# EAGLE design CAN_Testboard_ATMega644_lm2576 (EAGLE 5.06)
VOLTAGE: 16V

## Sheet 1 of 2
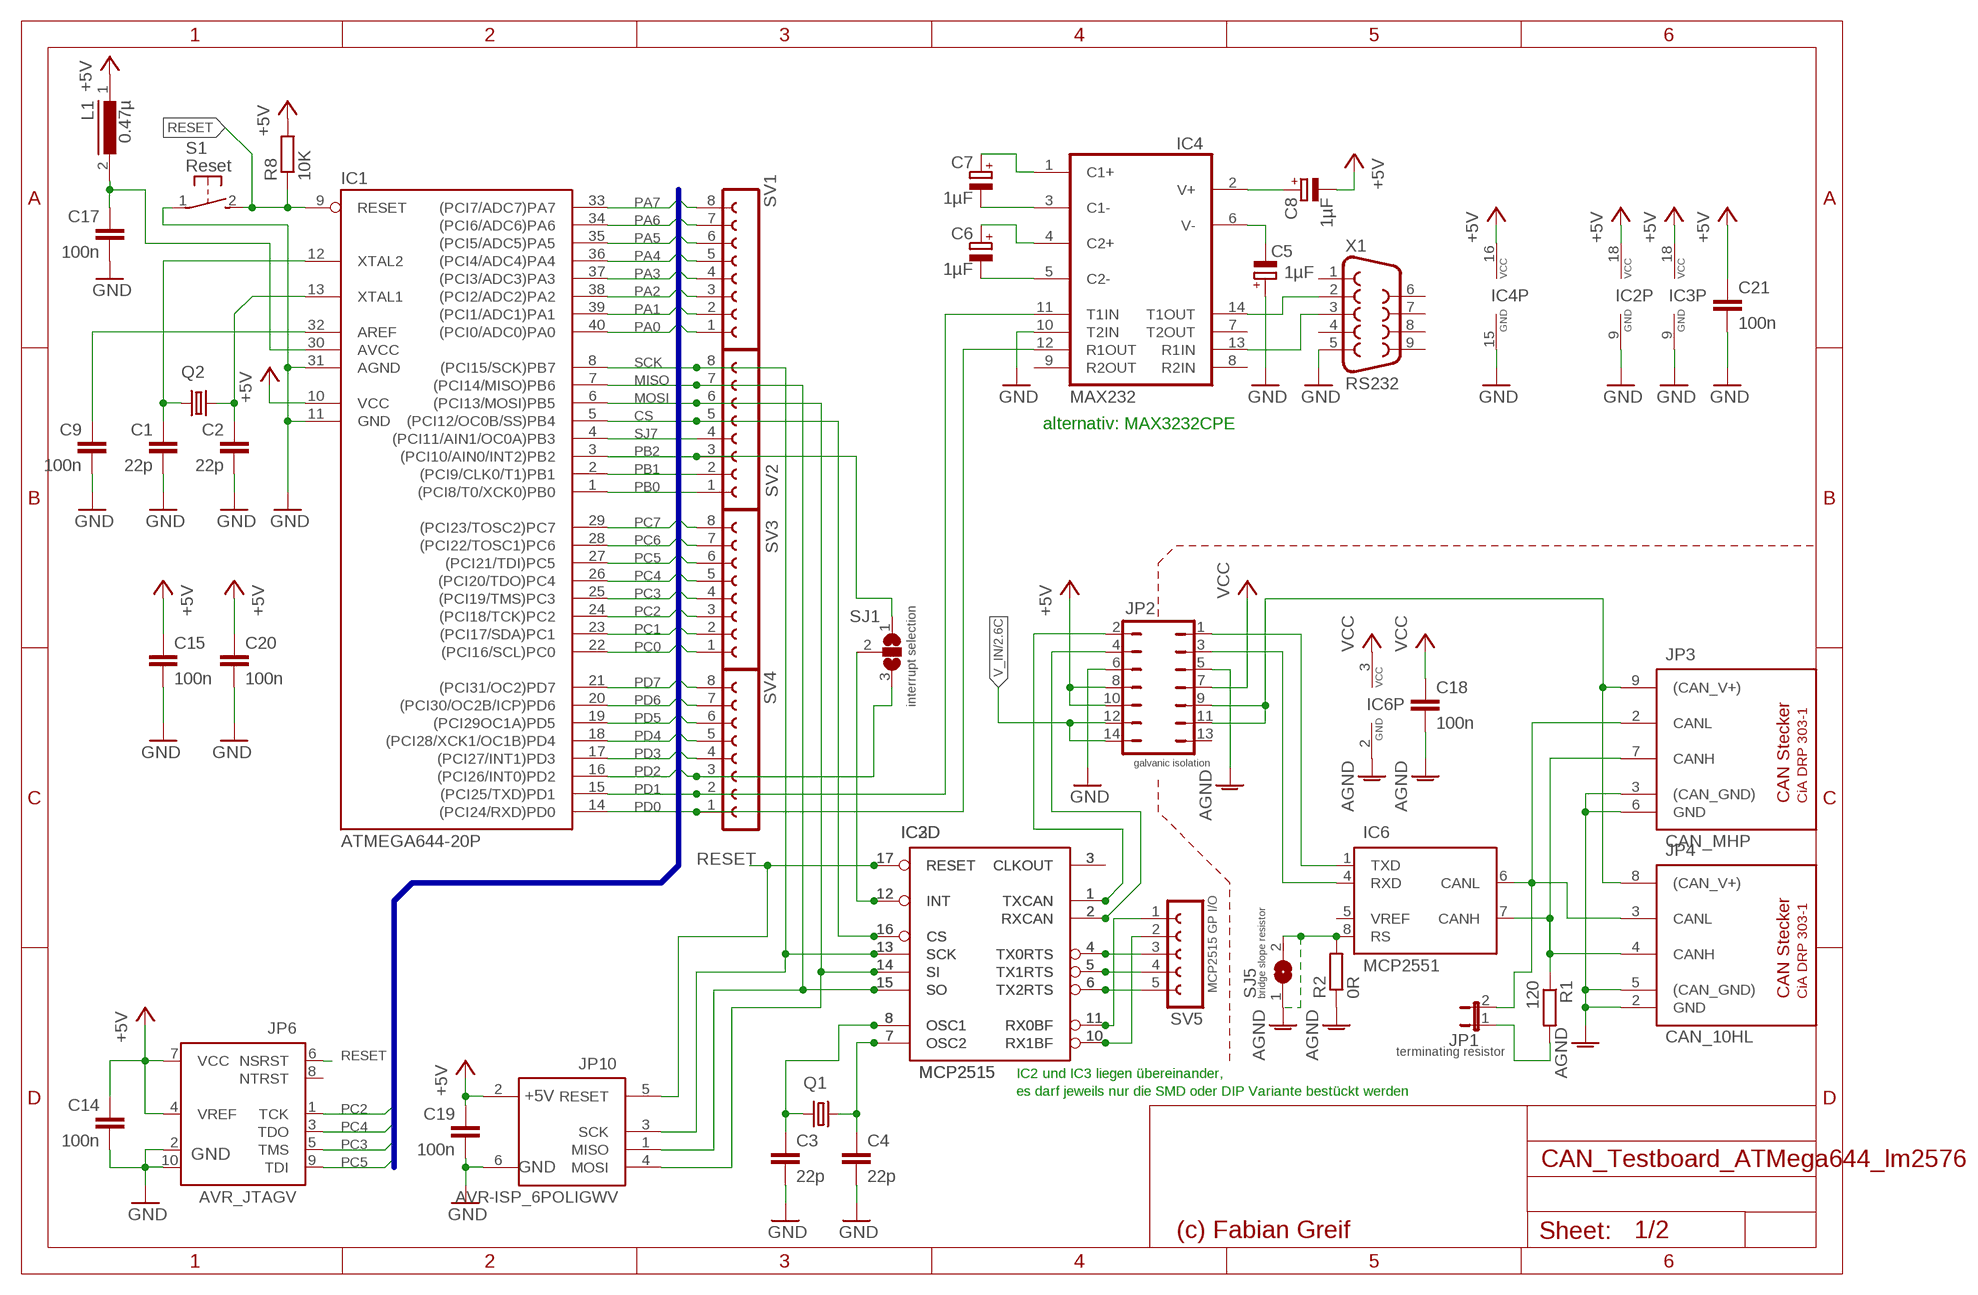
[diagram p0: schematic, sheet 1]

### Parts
C1  22p  C-EU025-024X044  [C025-024X044]
C2  22p  C-EU025-024X044  [C025-024X044]
C3  22p  C-EU025-024X044  [C025-024X044]
C4  22p  C-EU025-024X044  [C025-024X044]
C5  1µF  CPOL-EUE2.5-5  [E2,5-5]
C6  1µF  CPOL-EUE2.5-5  [E2,5-5]
C7  1µF  CPOL-EUE2.5-5  [E2,5-5]
C8  1µF  CPOL-EUE2.5-5  [E2,5-5]
C9  100n  C-EU025-024X044  [C025-024X044]
C14  100n  C-EU025-024X044  [C025-024X044]
C15  100n  C-EU025-024X044  [C025-024X044]
C17  100n  C-EU025-024X044  [C025-024X044]
C18  100n  C-EU025-024X044  [C025-024X044]
C19  100n  C-EU025-024X044  [C025-024X044]
C20  100n  C-EU025-024X044  [C025-024X044]
C21  100n  C-EU025-024X044  [C025-024X044]
IC1  ATMEGA644-20P  [DIL40]
IC2  MCP2515  MCP2515P  [DIL18]
IC3  MCP2515  MCP2515SO  [SO-18W]
IC4  MAX232  [DIL16]
IC6  MCP2551  PCA82C250  [DIL08]
JP1  terminating resistor  JP1E  [JP1]
JP2  galvanic isolation  JP7Q  [JP7Q]
JP3  CAN_MHP  [M09HP]
JP4  CAN_10HL  [ML10L]
JP6  AVR_JTAGV  [ML10L]
JP10  AVR-ISP_6POLIGWV  [ML6L]
L1  0.47µ  BC12  [BC12]
Q1  16.000  CRYTALHC49U-V  [HC49U-V]
Q2  14.7456  CRYTALHC49U-V  [HC49U-V]
R1  120  R-EU_0207/7  [0207/7]
R2  0R  R-EU_0207/7  [0207/7]
R8  10K  R-EU_0207/7  [0207/7]
S1  Reset  31-XX  [B3F-31XX]
SJ1  interrupt selection  SJ2W  [SJ_2]
SJ5  bridge slope resistor  SJ  [SJ]
SV1  Port A  FE08-1  [FE08]
SV2  Port B  FE08-1  [FE08]
SV3  Port C  FE08-1  [FE08]
SV4  Port D  FE08-1  [FE08]
SV5  MCP2515 GP I/O  FE05-1  [FE05-1]
X1  RS232  F09HP  [F09HP]

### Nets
+5V: C8.- C14.1 C15.1 C19.1 C20.1 C21.1 IC1.10(VCC) IC2.18(P:VCC) IC3.18(P:VCC) IC4.16(VCC) JP2.8 JP2.10 JP6.4(VREF) JP6.7(VCC) JP10.2(+5V) L1.1 R8.2 ; also sheet 2
AGND: C18.2 IC6.2(GND) JP2.5 JP3.3((CAN_GND)) JP3.6(GND) JP4.2(GND) JP4.5((CAN_GND)) R2.1 SJ5.1
AVCC: C17.1 IC1.30(AVCC) L1.2
CLKOUT: C2.1 IC1.13(XTAL1) Q2.2
CLKOUT1: IC2.3(D:CLKOUT) IC3.3(D:CLKOUT)
CS: IC1.5((PCI12/OC0B/SS)PB4) IC2.16(D:CS) IC3.16(D:CS) SV2.5 ; also sheet 2
GND: C1.2 C2.2 C3.2 C4.2 C5.+ C9.2 C14.2 C15.2 C17.2 C19.2 C20.2 C21.2 IC1.11(GND) IC1.31(AGND) IC2.9(P:GND) IC3.9(P:GND) IC4.10(T2IN) IC4.15(GND) JP2.6 JP6.2(GND) JP6.10(GND) JP10.6(GND) S1.1(P) X1.5 ; also sheet 2
MISO: IC1.7((PCI14/MISO)PB6) IC2.15(D:SO) IC3.15(D:SO) JP10.1(MISO) SV2.7 ; also sheet 2
MOSI: IC1.6((PCI13/MOSI)PB5) IC2.14(D:SI) IC3.14(D:SI) JP10.4(MOSI) SV2.6 ; also sheet 2
N$1: C6.- IC4.5(C2-)
N$2: C6.+ IC4.4(C2+)
N$3: C7.- IC4.3(C1-)
N$4: C8.+ IC4.2(V+)
N$5: C5.- IC4.6(V-)
N$8: C7.+ IC4.1(C1+)
N$9: C4.1 IC2.7(D:OSC2) IC3.7(D:OSC2) Q1.2
N$10: IC6.4(RXD) JP2.3
N$11: IC2.2(D:RXCAN) IC3.2(D:RXCAN) JP2.4
N$12: C3.1 IC2.8(D:OSC1) IC3.8(D:OSC1) Q1.1
N$13: C9.1 IC1.32(AREF)
N$17: IC6.8(RS) R2.2 SJ5.2
N$18: C1.1 IC1.12(XTAL2) Q2.1
N$20: IC2.12(D:INT) IC3.12(D:INT) SJ1.2
N$22: IC6.6(CANL) JP1.2 JP3.2(CANL) JP4.3(CANL)
N$23: IC6.7(CANH) JP3.7(CANH) JP4.4(CANH) R1.1
N$24: IC6.1(TXD) JP2.1
N$25: JP1.1 R1.2
N$26: IC2.4(D:TX0RTS) IC3.4(D:TX0RTS) SV5.3
N$27: IC2.5(D:TX1RTS) IC3.5(D:TX1RTS) SV5.4
N$28: IC2.6(D:TX2RTS) IC3.6(D:TX2RTS) SV5.5
N$29: IC2.11(D:RX0BF) IC3.11(D:RX0BF) SV5.1
N$30: IC2.10(D:RX1BF) IC3.10(D:RX1BF) SV5.2
N$31: IC2.1(D:TXCAN) IC3.1(D:TXCAN) JP2.2
PA0: IC1.40((PCI0/ADC0)PA0) SV1.1 ; also sheet 2
PA1: IC1.39((PCI1/ADC1)PA1) SV1.2 ; also sheet 2
PA2: IC1.38((PCI2/ADC2)PA2) SV1.3 ; also sheet 2
PA3: IC1.37((PCI3/ADC3)PA3) SV1.4 ; also sheet 2
PA4: IC1.36((PCI4/ADC4)PA4) SV1.5 ; also sheet 2
PA5: IC1.35((PCI5/ADC5)PA5) SV1.6 ; also sheet 2
PA6: IC1.34((PCI6/ADC6)PA6) SV1.7 ; also sheet 2
PA7: IC1.33((PCI7/ADC7)PA7) SV1.8 ; also sheet 2
PB0: IC1.1((PCI8/T0/XCK0)PB0) SV2.1 ; also sheet 2
PB1: IC1.2((PCI9/CLK0/T1)PB1) SV2.2 ; also sheet 2
PB2: IC1.3((PCI10/AIN0/INT2)PB2) SJ1.1 SV2.3 ; also sheet 2
PC0: IC1.22((PCI16/SCL)PC0) SV3.1 ; also sheet 2
PC1: IC1.23((PCI17/SDA)PC1) SV3.2 ; also sheet 2
PC2: IC1.24((PCI18/TCK)PC2) JP6.1(TCK) SV3.3 ; also sheet 2
PC3: IC1.25((PCI19/TMS)PC3) JP6.5(TMS) SV3.4 ; also sheet 2
PC4: IC1.26((PCI20/TDO)PC4) JP6.3(TDO) SV3.5 ; also sheet 2
PC5: IC1.27((PCI21/TDI)PC5) JP6.9(TDI) SV3.6 ; also sheet 2
PC6: IC1.28((PCI22/TOSC1)PC6) SV3.7 ; also sheet 2
PC7: IC1.29((PCI23/TOSC2)PC7) SV3.8 ; also sheet 2
PD0: IC1.14((PCI24/RXD)PD0) IC4.12(R1OUT) SV4.1 ; also sheet 2
PD1: IC1.15((PCI25/TXD)PD1) IC4.11(T1IN) SV4.2 ; also sheet 2
PD2: IC1.16((PCI26/INT0)PD2) SJ1.3 SV4.3 ; also sheet 2
PD3: IC1.17((PCI27/INT1)PD3) SV4.4 ; also sheet 2
PD4: IC1.18((PCI28/XCK1/OC1B)PD4) SV4.5 ; also sheet 2
PD5: IC1.19((PCI29OC1A)PD5) SV4.6 ; also sheet 2
PD6: IC1.20((PCI30/OC2B/ICP)PD6) SV4.7 ; also sheet 2
PD7: IC1.21((PCI31/OC2)PD7) SV4.8 ; also sheet 2
R_IN: IC4.13(R1IN) X1.3
RESET: IC1.9(RESET) IC2.17(D:RESET) IC3.17(D:RESET) JP6.6(NSRST) JP10.5(RESET) R8.1 S1.2(S)
SCK: IC1.8((PCI15/SCK)PB7) IC2.13(D:SCK) IC3.13(D:SCK) JP10.3(SCK) SV2.8 ; also sheet 2
SJ7: IC1.4((PCI11/AIN1/OC0A)PB3) SV2.4 ; also sheet 2
T_OUT: IC4.14(T1OUT) X1.2
V_CAN: JP2.9 JP2.11 JP3.9((CAN_V+)) JP4.8((CAN_V+))
V_IN: JP2.12 JP2.14 ; also sheet 2
VCC: C18.1 IC6.3(VCC) JP2.7
Unconnected: IC4.7(T2OUT) IC4.8(R2IN) IC4.9(R2OUT) IC6.5(VREF) JP2.13 JP6.8(NTRST) X1.1 X1.4 X1.6 X1.7 X1.8 X1.9

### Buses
PA[0..7],PC[0..7],PD[0..7]

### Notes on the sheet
- alternativ: MAX3232CPE
- IC2 und IC3 liegen übereinander,
- es darf jeweils nur die SMD oder DIP Variante bestückt werden
- (c) Fabian Greif

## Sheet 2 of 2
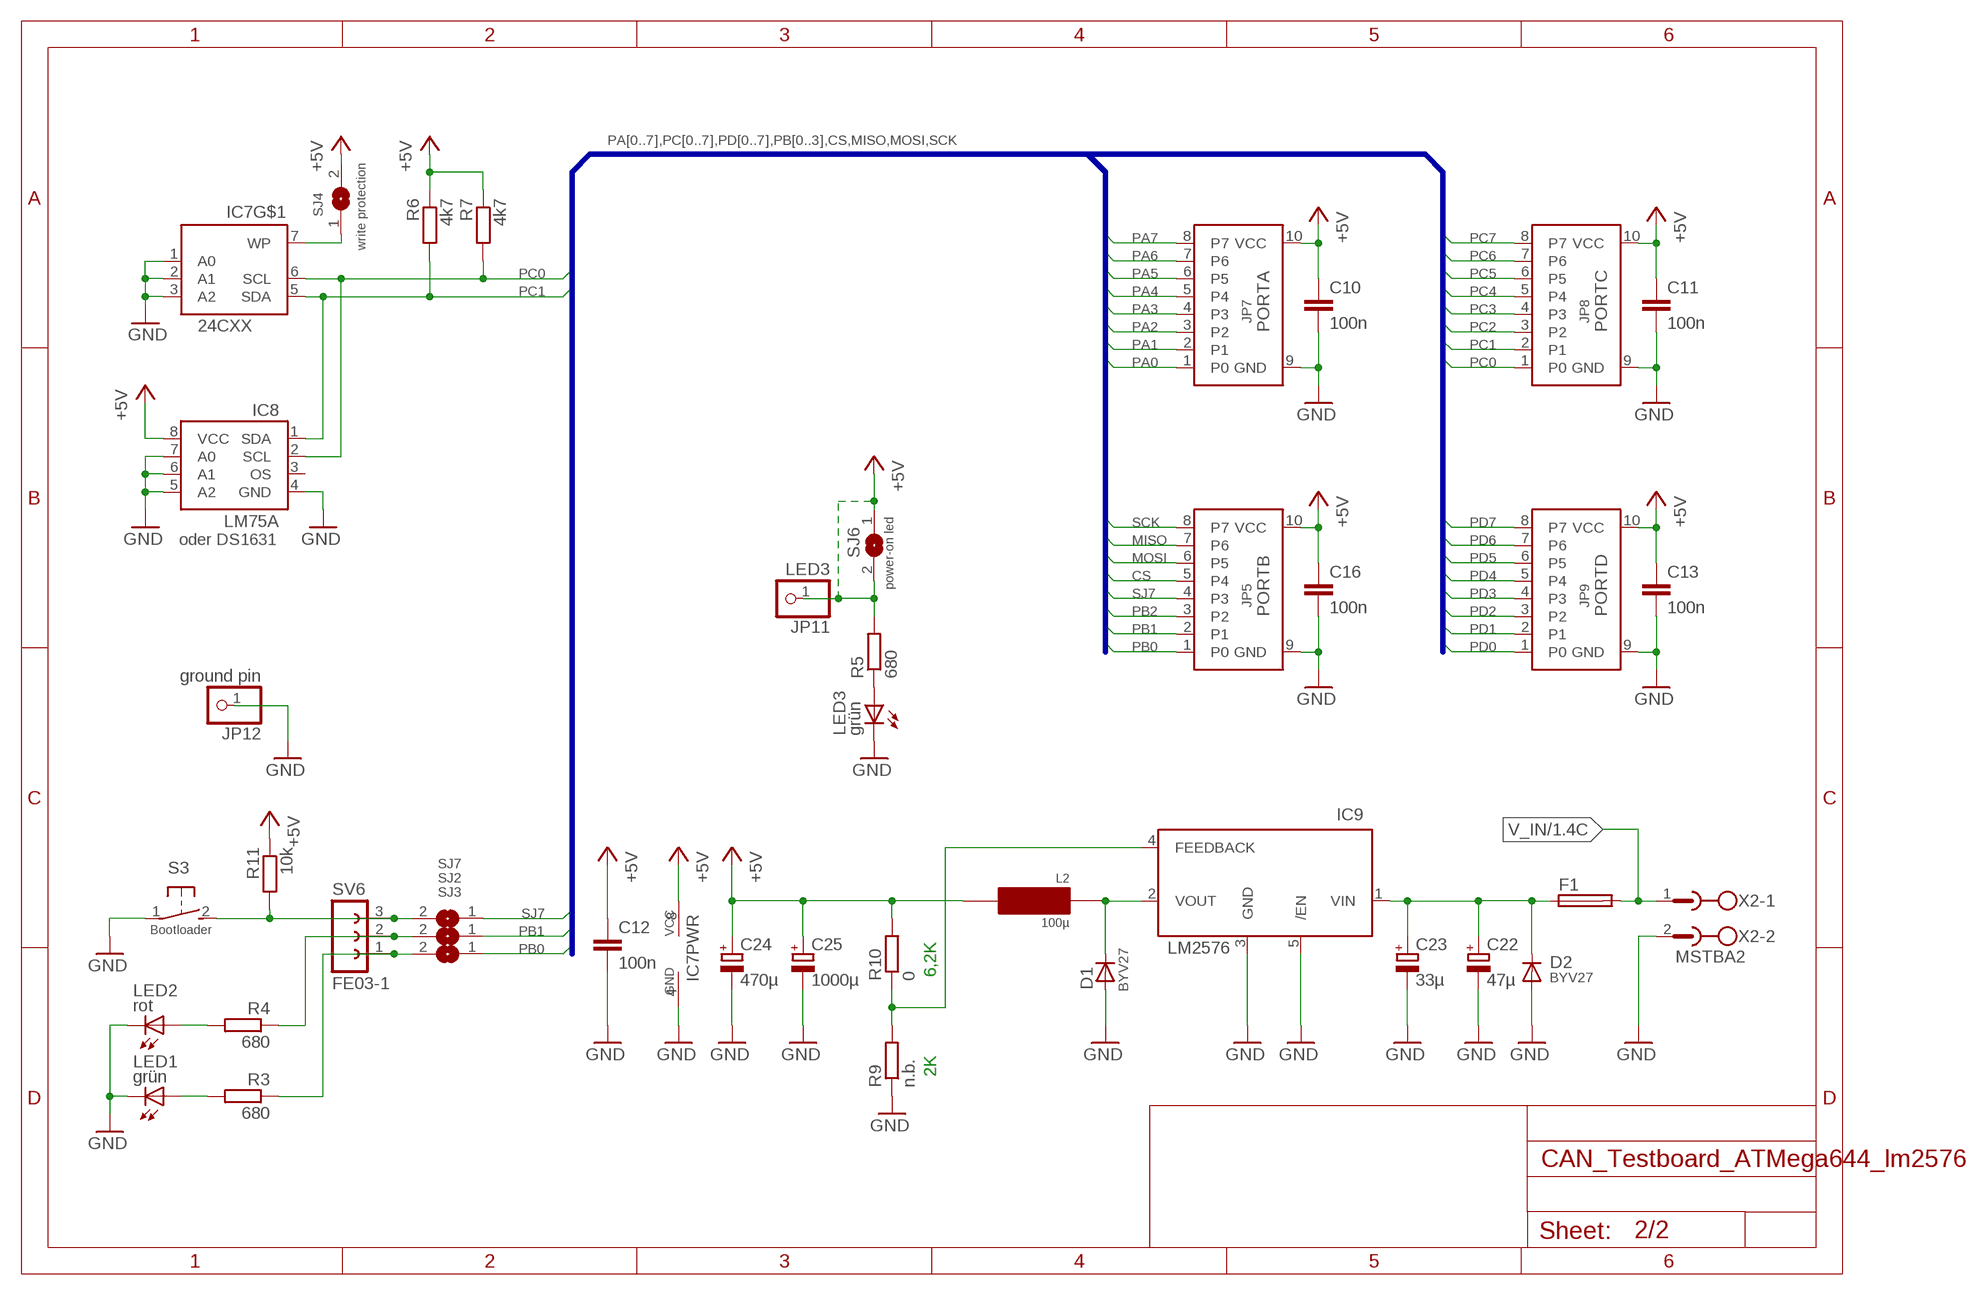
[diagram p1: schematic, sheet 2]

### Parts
C10  100n  C-EU025-024X044  [C025-024X044]
C11  100n  C-EU025-024X044  [C025-024X044]
C12  100n  C-EU025-024X044  [C025-024X044]
C13  100n  C-EU025-024X044  [C025-024X044]
C16  100n  C-EU025-024X044  [C025-024X044]
C22  47µ  CPOL-EUE  [PANASONIC_E]
C23  33µ  CPOL-EUD  [PANASONIC_D]
C24  470µ  CPOL-EUF  [PANASONIC_F]
C25  1000µ  CPOL-EUG  [PANASONIC_G]
D1  BYV27  [SOD57-10]
D2  BYV27  [SOD57-10]
F1  FUSE-SMD  [SMD-HASF]
IC7  24CXX  ST24CXX_SMD  [SO-08]
IC8  LM75A  [SO8]
IC9  LM2576  [TO220-52]
JP5  PORTB  PORT  [ML10]
JP7  PORTA  PORT  [ML10]
JP8  PORTC  PORT  [ML10]
JP9  PORTD  PORT  [ML10]
JP11  LED3  PINHD-1X1  [1X01]
JP12  ground pin  PINHD-1X1  [1X01]
L2  100µ  INDUCTOR-PIS47XX  [L-PIS47XX]
LED1  grün  LED3MM  [LED3MM]
LED2  rot  LED3MM  [LED3MM]
LED3  grün  LED3MM  [LED3MM]
R3  680  R-EU_0207/7  [0207/7]
R4  680  R-EU_0207/7  [0207/7]
R5  680  R-EU_0207/7  [0207/7]
R6  4k7  R-EU_0207/7  [0207/7]
R7  4k7  R-EU_0207/7  [0207/7]
R9  n.b.  R-EU_0207/7  [0207/7]
R10  0  R-EU_0207/7  [0207/7]
R11  10k  R-EU_0207/7  [0207/7]
S3  Bootloader  31-XX  [B3F-31XX]
SJ2  enable LED2  SJ  [SJ]
SJ3  enable LED1  SJ  [SJ]
SJ4  write protection  SJ  [SJ]
SJ6  power-on led  SJ  [SJ]
SJ7  enable S3  SJ  [SJ]
SV6  FE03-1  [FE03-1]
X2  MSTBA2  [MSTBA2]

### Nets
+5V: C10.1 C11.1 C12.1 C13.1 C16.1 C24.+ C25.+ IC7.8(PWR:VCC) IC8.8(VCC) JP5.10(VCC) JP7.10(VCC) JP8.10(VCC) JP9.10(VCC) JP11.1 L2.2 R5.2 R6.1 R7.1 R10.2 R11.1 SJ4.2 SJ6.1 SJ6.2 ; also sheet 1
CS: JP5.5(P4) ; also sheet 1
GND: C10.2 C11.2 C12.2 C13.2 C16.2 C22.- C23.- C24.- C25.- D1.A D2.A IC7.1(A0) IC7.2(A1) IC7.3(A2) IC7.4(PWR:GND) IC8.4(GND) IC8.5(A2) IC8.6(A1) IC8.7(A0) IC9.3(GND) IC9.5(/EN) JP5.9(GND) JP7.9(GND) JP8.9(GND) JP9.9(GND) JP12.1 LED1.K(C) LED2.K(C) LED3.K(C) R9.1 S3.1(P) X2.2 ; also sheet 1
LED4: R4.1 SJ2.2 SV6.2
LED5: R3.1 SJ3.2 SV6.1
MISO: JP5.7(P6) ; also sheet 1
MOSI: JP5.6(P5) ; also sheet 1
N$15: LED3.A R5.1
N$16: C22.+ C23.+ D2.C F1.1 IC9.1(VIN)
N$19: IC9.4(FEEDBACK) R9.2 R10.1
N$48: IC7.7(WP) SJ4.1
N$105: D1.C IC9.2(VOUT) L2.1
N$108: R11.2 S3.2(S) SJ7.2 SV6.3
N$168: LED2.A R4.2
N$169: LED1.A R3.2
PA0: JP7.1(P0) ; also sheet 1
PA1: JP7.2(P1) ; also sheet 1
PA2: JP7.3(P2) ; also sheet 1
PA3: JP7.4(P3) ; also sheet 1
PA4: JP7.5(P4) ; also sheet 1
PA5: JP7.6(P5) ; also sheet 1
PA6: JP7.7(P6) ; also sheet 1
PA7: JP7.8(P7) ; also sheet 1
PB0: JP5.1(P0) SJ3.1 ; also sheet 1
PB1: JP5.2(P1) SJ2.1 ; also sheet 1
PB2: JP5.3(P2) ; also sheet 1
PC0: IC7.6(SCL) IC8.2(SCL) JP8.1(P0) R7.2 ; also sheet 1
PC1: IC7.5(SDA) IC8.1(SDA) JP8.2(P1) R6.2 ; also sheet 1
PC2: JP8.3(P2) ; also sheet 1
PC3: JP8.4(P3) ; also sheet 1
PC4: JP8.5(P4) ; also sheet 1
PC5: JP8.6(P5) ; also sheet 1
PC6: JP8.7(P6) ; also sheet 1
PC7: JP8.8(P7) ; also sheet 1
PD0: JP9.1(P0) ; also sheet 1
PD1: JP9.2(P1) ; also sheet 1
PD2: JP9.3(P2) ; also sheet 1
PD3: JP9.4(P3) ; also sheet 1
PD4: JP9.5(P4) ; also sheet 1
PD5: JP9.6(P5) ; also sheet 1
PD6: JP9.7(P6) ; also sheet 1
PD7: JP9.8(P7) ; also sheet 1
SCK: JP5.8(P7) ; also sheet 1
SJ7: JP5.4(P3) SJ7.1 ; also sheet 1
V_IN: F1.2 X2.1 ; also sheet 1
Unconnected: IC8.3(OS)

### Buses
PA[0..7],PC[0..7],PD[0..7],PB[0..3],CS,MISO,MOSI,SCK

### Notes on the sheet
- oder DS1631
- 6,2K
- 2K

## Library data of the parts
C1-C4 C9-C21 = rcl:C-EU: CAPACITOR, European symbol
C5-C8 C22-C25 = rcl:CPOL-EU: POLARIZED CAPACITOR, European symbol
D1 D2 = diode:BYV27: DIODE
F1 = rca_sontiges:FUSE: Fuse
IC1 = avr:ATMEGA644*P: MICROCONTROLLER 64 kBytes FLASH 4 kBytes SRAM 2 kBytes EEPROM DUAL USART 8-channel 10 bit ADC
IC2 = andereBauteile:MCP2515: MC2515 Stand-Alone CAN Controller With SPI Interface
IC3 = rca_ic:MCP2515: MC2515 Stand-Alone CAN Controller With SPI Interface
IC4 = maxim:MAX232: RS232 TRANSEIVER
IC6 = andereBauteile:PCA82C250: PCA82C250 CAN Bustreiber
IC7 = rca_sontiges:ST24CXX: I²C EEPROM Bei den Atmeltypen ist der A2-Pin nicht angeschlossen! Bisher überprüfte Größen: ST24C32 (4 kByte) ST24C64 (8 kByte) ST24C128 (16 kByte) ST24C256 (32 kByte)
IC8 = nxp:LM75A
IC9 = rca_spgversorgung:LM257*: LM2575/6 1/3A Step-Down Voltage Regulator
JP1 = jumper:JP1E: JUMPER
JP2 = jumper:JP7Q: JUMPER
JP3 JP4 = rca_stecker:CAN_: CAN Stecker nach CiA DRP 303-1
JP5 JP7-JP9 = stecker-definitionen:PORT: Datenportstecker Kompatibel zu den Steckern des STK500
JP6 = stecker-definitionen:AVR_JTAG: AVR JTAG Adapter Zum Programmieren/Simulieren von AVRs in der Schaltung
JP10 = rca_stecker:AVR-ISP_6POLIG: ISP (In System Programming) Stecker für AVRs Über diesen Anschluß kann ein AVR mit einem Standard ISP-Kabel direkt an einen Parallelport des PC´s angeschlossen und programmiert werden.
JP11 JP12 = pinhead:PINHD-1X1: PIN HEADER
L1 = inductors:BC12: INDUCTOR
L2 = rca_sontiges:INDUCTOR: SMD-Power-Induktivitäten
LED1-LED3 = led:LED: LED
Q1 Q2 = crystal:CRYTAL: CRYSTAL
R1-R11 = rcl:R-EU_: RESISTOR, European symbol
S1 S3 = switch-omron:31-XX: OMRON SWITCH
SJ1 = jumper:SJ2W: SMD solder JUMPER
SJ2-SJ7 = jumper:SJ: SMD solder JUMPER
SV1-SV4 = con-lsta:FE08-1: FEMALE HEADER
SV5 = con-lsta:FE05-1: FEMALE HEADER
SV6 = con-lsta:FE03-1
X1 = con-subd:F09: SUB-D
X2 = con-phoenix-508:MSTBA2: PHOENIX

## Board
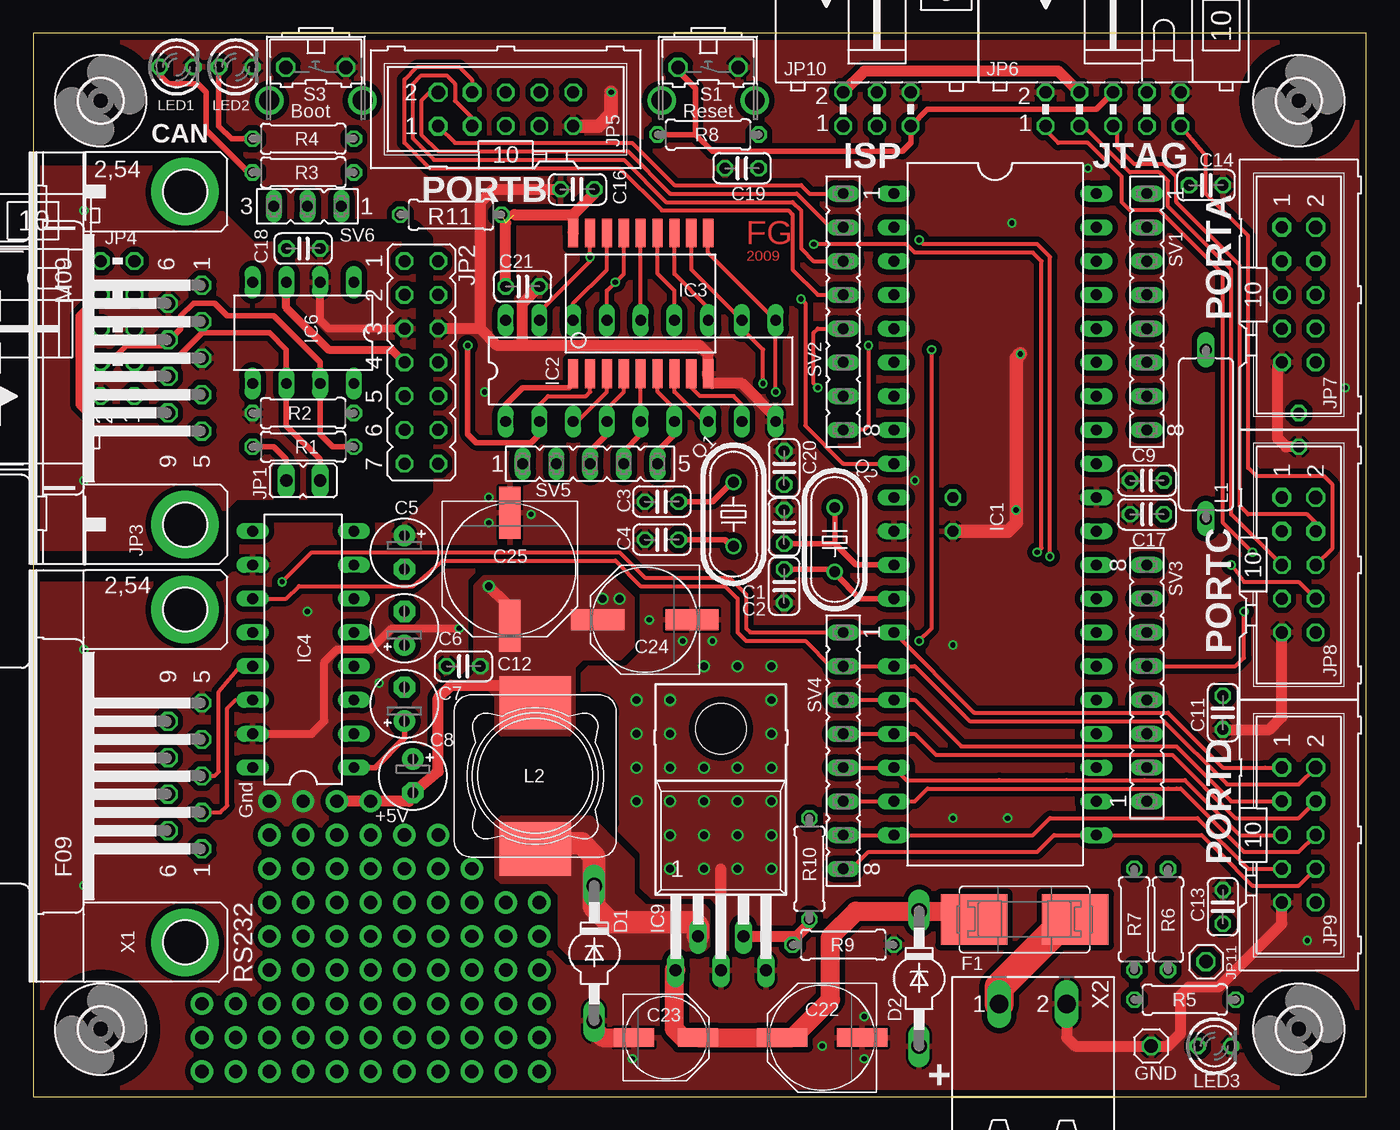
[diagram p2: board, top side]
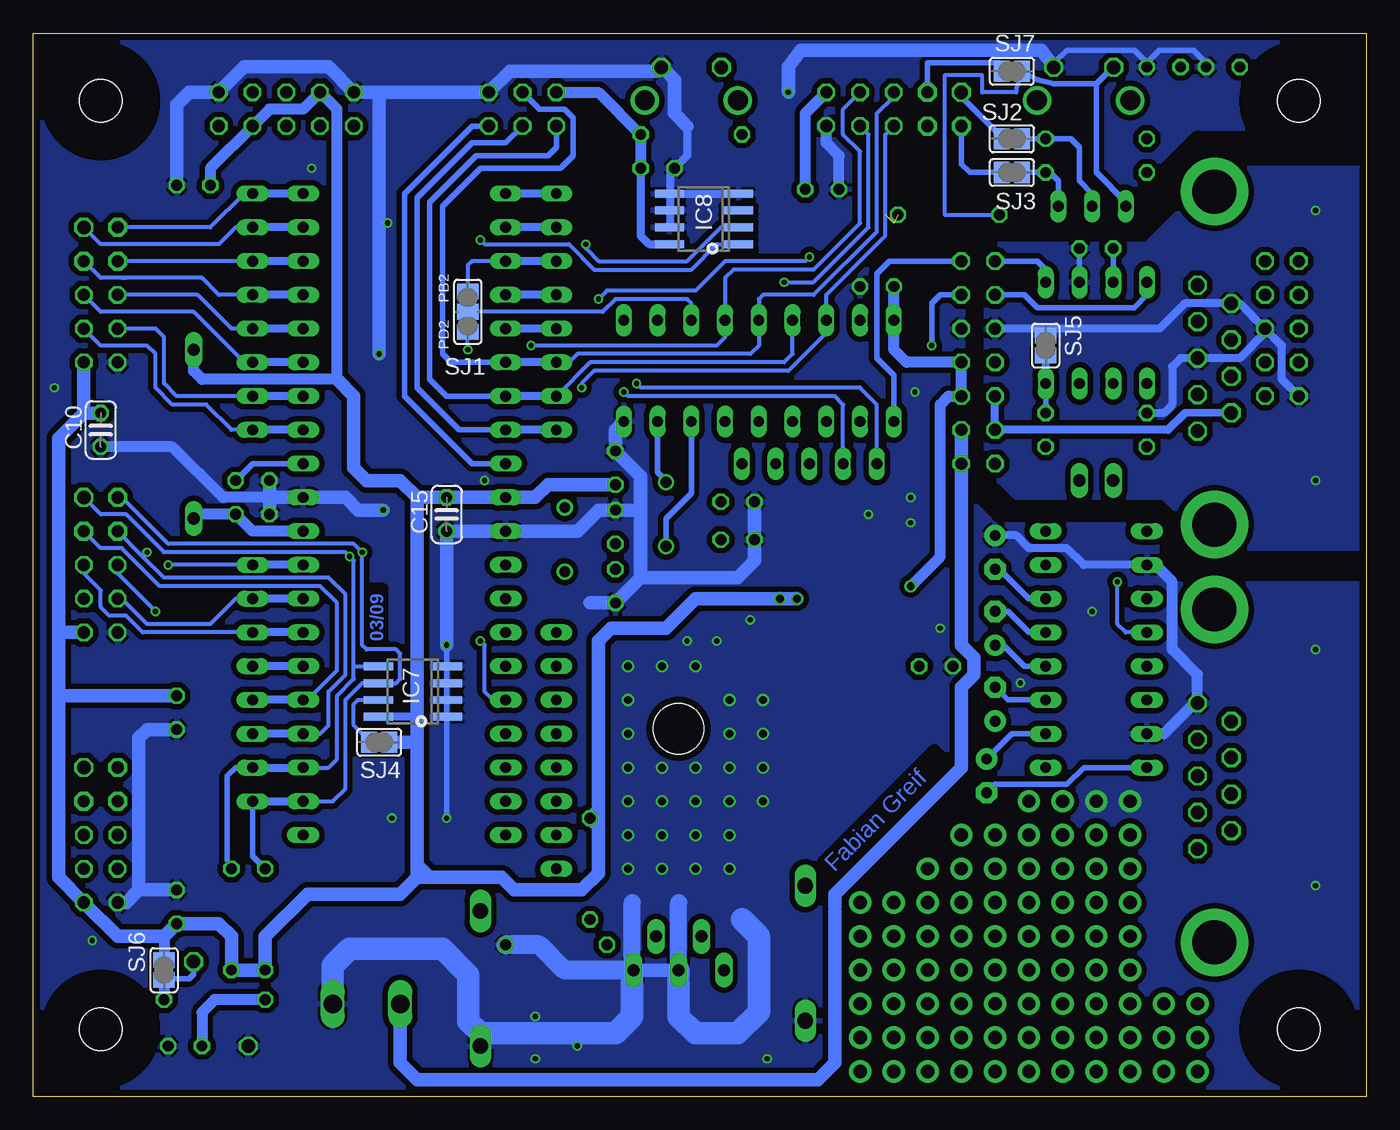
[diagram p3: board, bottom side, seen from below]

Size 100.33 x 80.01 mm. Coordinates in mm from the lower left corner, seen from the top.
Outline: 0,0 100.33,0 100.33,80.01 0,80.01 0,0
Copper layers (1*16): Top 0.035mm / dielectric 1.5mm / Bottom 0.035mm
Design rules "PCB-POOL": minimum track width 6mil, minimum drill 12mil, track to track 6mil, track to pad 6mil, pad to pad 6mil, via to via 6mil, smd to smd 6mil, copper to edge 20mil, drill to drill 8mil, minimum pad ring 8mil, minimum via ring 6mil, stop-mask expansion 3mil, vias tented up to drill 20mil, thermal gap 8mil
tRestrict: 22 lines
bRestrict: 14 lines

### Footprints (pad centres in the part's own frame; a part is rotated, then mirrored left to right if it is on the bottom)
C025-024X044 = drill 0.813 octagon: 1 -1.27,0; 2 1.27,0
E2,5-5 = drill 0.813 pad 1.6 round: + -1.27,0 | drill 0.813 pad 1.6 octagon: - 1.27,0
PANASONIC_E = smd 3.8 x 1.4: + 3,0; - -3,0
PANASONIC_D = smd 3 x 1.4: + 2.4,0; - -2.4,0
PANASONIC_F = smd 4 x 1.6: + 3.55,0; - -3.55,0
PANASONIC_G = smd 3.9 x 1.6: + 4.25,0; - -4.25,0
SOD57-10 = drill 1.194 long: A 5.08,0; C -5.08,0
SMD-HASF = smd 5 x 3.81: 1 -3.81,0; 2 3.81,0
DIL40 = drill 0.813 long: 1 -24.13,-7.62; 2 -21.59,-7.62; 3 -19.05,-7.62; 4 -16.51,-7.62; 5 -13.97,-7.62; 6 -11.43,-7.62; 7 -8.89,-7.62; 8 -6.35,-7.62; 9 -3.81,-7.62; 10 -1.27,-7.62; 11 1.27,-7.62; 12 3.81,-7.62; 13 6.35,-7.62; 14 8.89,-7.62; 15 11.43,-7.62; 16 13.97,-7.62; 17 16.51,-7.62; 18 19.05,-7.62; 19 21.59,-7.62; 20 24.13,-7.62; 21 24.13,7.62; 22 21.59,7.62; 23 19.05,7.62; 24 16.51,7.62; 25 13.97,7.62; 26 11.43,7.62; 27 8.89,7.62; 28 6.35,7.62; 29 3.81,7.62; 30 1.27,7.62; 31 -1.27,7.62; 32 -3.81,7.62; 33 -6.35,7.62; 34 -8.89,7.62; 35 -11.43,7.62; 36 -13.97,7.62; 37 -16.51,7.62; 38 -19.05,7.62; 39 -21.59,7.62; 40 -24.13,7.62
DIL18 = drill 0.813 long: 1 -10.16,-3.81; 2 -7.62,-3.81; 3 -5.08,-3.81; 4 -2.54,-3.81; 5 0,-3.81; 6 2.54,-3.81; 7 5.08,-3.81; 8 7.62,-3.81; 9 10.16,-3.81; 10 10.16,3.81; 11 7.62,3.81; 12 5.08,3.81; 13 2.54,3.81; 14 0,3.81; 15 -2.54,3.81; 16 -5.08,3.81; 17 -7.62,3.81; 18 -10.16,3.81
SO-18W = smd 0.762 x 2.159: 1 -5.08,-5.296; 2 -3.81,-5.296; 3 -2.54,-5.296; 4 -1.27,-5.296; 5 0,-5.296; 6 1.27,-5.296; 7 2.54,-5.296; 8 3.81,-5.296; 9 5.08,-5.296; 10 5.08,5.296; 11 3.81,5.296; 12 2.54,5.296; 13 1.27,5.296; 14 0,5.296; 15 -1.27,5.296; 16 -2.54,5.296; 17 -3.81,5.296; 18 -5.08,5.296
DIL16 = drill 0.813 long: 1 -8.89,-3.81; 2 -6.35,-3.81; 3 -3.81,-3.81; 4 -1.27,-3.81; 5 1.27,-3.81; 6 3.81,-3.81; 7 6.35,-3.81; 8 8.89,-3.81; 9 8.89,3.81; 10 6.35,3.81; 11 3.81,3.81; 12 1.27,3.81; 13 -1.27,3.81; 14 -3.81,3.81; 15 -6.35,3.81; 16 -8.89,3.81
DIL08 = drill 0.813 long: 1 -3.81,-3.81; 2 -1.27,-3.81; 3 1.27,-3.81; 4 3.81,-3.81; 5 3.81,3.81; 6 1.27,3.81; 7 -1.27,3.81; 8 -3.81,3.81
SO-08 = smd 0.6 x 2.2: 1 -1.905,-2.6; 2 -0.635,-2.6; 3 0.635,-2.6; 4 1.905,-2.6; 5 1.905,2.6; 6 0.635,2.6; 7 -0.635,2.6; 8 -1.905,2.6
SO8 = smd 0.6 x 2.2: 1 -1.905,-2.6; 2 -0.635,-2.6; 3 0.635,-2.6; 4 1.905,-2.6; 5 1.905,2.6; 6 0.635,2.6; 7 -0.635,2.6; 8 -1.905,2.6
TO220-52 = drill 0.9 long: 1 -3.404,-2.54; 2 -1.702,0; 3 0,-2.54; 4 1.702,0; 5 3.404,-2.54 | hole 3.8: 0,15.615
JP1 = drill 0.914 long: 1 0,-1.27; 2 0,1.27
JP7Q = drill 0.914 octagon: 1 -7.62,-1.27; 2 -7.62,1.27; 3 -5.08,-1.27; 4 -5.08,1.27; 5 -2.54,-1.27; 6 -2.54,1.27; 7 0,-1.27; 8 0,1.27; 9 2.54,-1.27; 10 2.54,1.27; 11 5.08,-1.27; 12 5.08,1.27; 13 7.62,-1.27; 14 7.62,1.27
M09HP = drill 1.016 octagon: 1 -5.486,1.27; 2 -2.743,1.27; 3 0,1.27; 4 2.743,1.27; 5 5.486,1.27; 6 -4.115,-1.27; 7 -1.372,-1.27; 8 1.372,-1.27; 9 4.115,-1.27 | drill 3.302 pad 5.08 round: G1 -12.522,0; G2 12.522,0
ML10L = drill 0.914 octagon: 1 -5.08,-1.27; 2 -5.08,1.27; 3 -2.54,-1.27; 4 -2.54,1.27; 5 0,-1.27; 6 0,1.27; 7 2.54,-1.27; 8 2.54,1.27; 9 5.08,-1.27; 10 5.08,1.27
ML10 = drill 0.914 pad 1.422 octagon: 1 -5.08,-1.27; 3 -2.54,-1.27; 4 -2.54,1.27 | drill 1.016 pad 1.422 octagon: 2 -5.08,1.27 | drill 0.914 octagon: 5 0,-1.27; 6 0,1.27; 7 2.54,-1.27; 8 2.54,1.27; 9 5.08,-1.27; 10 5.08,1.27
ML6L = drill 0.914 octagon: 1 -2.54,-1.27; 2 -2.54,1.27; 3 0,-1.27; 4 0,1.27; 5 2.54,-1.27; 6 2.54,1.27
1X01 = drill 1.016 octagon: 1 0,0
BC12 = drill 0.914 long: 1 -6.35,0; 2 6.35,0
L-PIS47XX = smd 5.4 x 4: 1 0,5.5; 2 0,-5.5
LED3MM = drill 0.813 octagon: A -1.27,0; K 1.27,0
HC49U-V = drill 0.813 round: 1 -2.413,0; 2 2.413,0
0207/7 = drill 0.813 octagon: 1 -3.81,0; 2 3.81,0
B3F-31XX = drill 1.016 octagon: 1 -2.261,-1.245; 2 2.261,-1.245 | drill 1.499 pad 2.159 round: 3 -3.505,1.245; 4 3.505,1.245
SJ_2 = smd 1.168 x 1.6: 1 -1.524,0; 2 0,0; 3 1.524,0
SJ = smd 1.168 x 1.6: 1 -0.762,0; 2 0.762,0
FE08 = drill 0.813 long: 1 -8.89,0; 2 -6.35,0; 3 -3.81,0; 4 -1.27,0; 5 1.27,0; 6 3.81,0; 7 6.35,0; 8 8.89,0
FE05-1 = drill 0.813 long: 1 -5.08,0; 2 -2.54,0; 3 0,0; 4 2.54,0; 5 5.08,0
FE03-1 = drill 0.813 long: 1 -2.54,0; 2 0,0; 3 2.54,0
3,2 = hole 3.2: 0,0
F09HP = drill 1.016 octagon: 1 -5.486,-1.27; 2 -2.743,-1.27; 3 0,-1.27; 4 2.743,-1.27; 5 5.486,-1.27; 6 -4.115,1.27; 7 -1.372,1.27; 8 1.372,1.27; 9 4.115,1.27 | drill 3.302 pad 5.08 round: G1 -12.522,0; G2 12.522,0
MSTBA2 = drill 1.397 long: 1 -2.54,5.08; 2 2.54,5.08

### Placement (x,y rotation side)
C1  56.52,42.86 90 top
C2  56.52,38.42 270 top
C3  47.31,44.77 180 top
C4  47.31,41.91 180 top
C5  27.94,40.96 270 top
C6  27.94,35.24 90 top
C7  27.94,29.53 90 top
C8  28.57,24.13 270 top
C9  83.82,46.36 180 top
C10  95.25,50.16 270 bottom
C11  89.53,28.89 270 top
C12  32.38,32.39 180 top
C13  89.53,14.29 90 top
C14  88.27,68.58 0 top
C15  69.22,43.82 270 bottom
C16  40.96,68.26 180 top
C17  83.82,43.82 180 top
C18  20.32,63.82 0 top
C19  53.34,69.85 180 top
C20  56.52,47.31 90 top
C21  36.83,60.96 0 top
C22  59.37,4.45 180 top
C23  47.62,4.45 0 top
C24  46.04,35.88 180 top
C25  35.88,39.69 270 top
D1  42.23,10.79 270 top
D2  66.67,8.89 270 top
F1  74.61,13.34 0 top
IC1  72.39,43.82 270 top
IC2  45.72,54.61 0 top
IC3  45.72,59.69 0 top
IC4  20.32,33.66 90 top
IC6  20.32,57.47 180 top
IC7  71.75,30.48 90 bottom
IC8  49.85,66.04 90 bottom
IC9  51.75,12.06 0 top
JP1  20.32,46.36 270 top
JP2  29.21,55.25 270 top
JP3  11.43,55.56 270 top
JP4  6.35,57.79 90 top
JP5  35.56,74.3 0 top
JP6  81.28,74.3 0 top
JP7  95.25,60.33 270 top
JP8  95.25,40.01 270 top
JP9  95.25,19.68 270 top
JP10  63.5,74.3 0 top
JP11  88.27,10.16 0 top
JP12  84.14,3.81 0 top
L1  88.27,49.85 270 top
L2  37.78,24.13 180 top
LED1  10.79,77.47 0 top
LED2  15.24,77.47 0 top
LED3  88.9,3.81 0 top
Q1  52.7,43.82 270 top
Q2  60.33,41.91 270 top
R1  20.32,48.9 180 top
R2  20.32,51.44 0 top
R3  20.32,69.53 180 top
R4  20.32,72.07 180 top
R5  86.68,7.3 0 top
R6  85.41,13.34 90 top
R7  82.87,13.34 90 top
R8  50.8,72.39 0 top
R9  60.96,11.43 180 top
R10  58.42,17.14 90 top
R11  31.43,66.36 180 top
S1  50.8,76.2 180 top
S3  21.27,76.2 180 top
SJ1  67.63,59.05 270 bottom
SJ2  26.67,72.07 0 bottom
SJ3  26.67,69.53 0 bottom
SJ4  74.3,26.67 0 bottom
SJ5  24.13,56.52 270 bottom
SJ6  90.49,9.53 270 bottom
SJ7  26.67,77.15 0 bottom
SV1  83.82,59.05 270 top
SV2  60.96,59.05 270 top
SV3  83.82,31.11 90 top
SV4  60.96,26.04 270 top
SV5  41.91,47.62 0 top
SV6  20.64,66.99 180 top
U$1  [3,2]  5.08,5.08 0 top
U$2  [3,2]  95.25,5.08 0 top
U$3  [3,2]  95.25,74.93 0 top
U$4  [3,2]  5.08,74.93 0 top
X1  11.43,24.13 90 top
X2  75.25,1.91 0 top

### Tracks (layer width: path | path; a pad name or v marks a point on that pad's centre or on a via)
+5V  (via drill 0.6, 1 pad 1.68)  (2 unrouted)
  Top 0.813: C21.1 35.56,65.72 | 40.64,65.09 IC3.18 40.64,66.36 | 36.2,66.36 40.64,66.36 | 40.64,66.36 42.23,67.94 C16.1 | 37.15,30.96 31.43,30.96 30.48,30 30.48,24.45 C8.- 28.26,22.22 v25.4,22.22 v22.86,22.22 | v34.29,38.42 35.56,37.15 | JP10.2 62.55,77.15 77.15,77.15 JP6.4
  Top 1.676: 36.51,29.21 L2.2 38.42,29.53 39.05,29.53
  Bottom 0.254: SJ6.1 90.49,8.89
  Bottom 0.406: C8.- 27.94,23.49 22.54,23.49 21.27,24.76 IC4.16 | JP11.1 88.27,9.21 88.58,8.89 90.49,8.89 SJ6.2
  Bottom 0.61: 71.44,28.57 IC7.8 | IC8.8 53.98,64.13 54.61,64.77 C19.1
  Bottom 0.813: L1.1 88.27,54.61 87.63,53.98 77.47,53.98 77.47,74.3 JP6.4 80.01,74.3 82.55,74.3 JP6.7 87,69.85 C14.1 | JP5.10 42.23,73.98 C16.1 | C21.1 IC2.18 35.56,56.2 34.61,55.25 JP2.8 JP2.10 31.43,52.71 32.07,52.07 32.07,40.64 v34.29,38.42 | 90.49,12.06 SJ6.1 | SJ6.2 R5.2 | C19.1 R8.2 57.78,75.56 JP10.2
  Bottom 1.016: 98.42,30.16 98.42,16.51 JP9.10 93.98,12.06 90.49,12.06 C13.1 86.36,13.02 85.41,12.06 R6.1 R7.1 82.87,12.06 79.69,15.24 72.71,15.24 71.44,16.51 | 98.42,30.16 98.42,34.93 | 98.42,34.93 JP8.10 | 98.42,30.16 C11.1 | 98.42,34.93 98.42,49.53 96.52,51.44 | 96.52,51.44 JP7.10 | 71.44,26.67 71.44,28.57 71.44,45.09 | 71.44,45.09 C15.1 IC1.10 62.55,45.09 61.59,46.04 C20.1 | 71.44,26.67 SJ4.2 | 71.44,16.51 71.44,17.46 | 71.44,17.46 71.44,26.67 | 96.52,51.44 C10.1 | 71.44,45.09 72.71,46.36 75.25,46.36 76.2,47.31 76.2,52.71 77.47,53.98 | 70.48,16.51 71.44,16.51 | 57.78,21.59 R10.2 57.78,20.32 | 57.78,21.59 57.78,34.29 56.83,35.24 52.7,35.24 50.48,37.47 v44.13,37.47 v42.86,37.47 | 70.48,16.51 71.44,17.46 | 57.78,20.32 57.78,16.83 59.05,15.56 64.14,15.56 65.09,16.51 70.48,16.51 | 57.78,20.32 57.78,21.59
  pour Top (isolate 0.406, no thermals): 33.34,38.42 33.34,31.75 32.7,31.11 33.97,31.11 34.29,30.8 34.92,30.16 34.92,27.62 35.24,27.3 40.32,27.3 40.64,27.78 40.64,32.39 41.27,33.02 44.13,33.02 45.09,33.97 45.09,37.47 43.5,39.05 33.97,39.05
AGND  (via drill 0.4)
  Top 0.61: IC6.2 21.59,58.42 22.23,57.79 JP2.5
  Bottom 0.254: 24.13,57.47 SJ5.1 | 24.13,57.15 24.13,55.56
  Bottom 0.406: IC6.2 C18.2
  Bottom 0.61: JP4.2 6.35,53.98 6.35,56.52 JP4.5 | JP4.5 9.53,59.69 JP3.6 | JP3.6 10.16,59.69 | JP4.5 7.62,57.47 9.53,55.56 JP3.3 13.97,55.56 14.61,54.93 14.61,52.07 15.24,51.44 R2.1 | SJ5.1 24.13,57.15 24.77,57.79 | 24.77,57.79 25.08,57.79 | JP3.6 13.66,59.68 | 13.66,59.68 13.65,59.69 | 13.66,59.68 15.56,57.79 24.13,57.79 | 24.13,57.79 24.77,57.79 | 24.13,57.79 24.13,57.47 | 24.13,57.79 JP2.5
  other vias: 3.81,46.36 3.81,66.67
  pour Bottom (isolate 0.406): -1.27,41.27 11.43,41.27 15.24,45.09 26.35,45.09 28.57,47.31 28.57,63.18 27.62,64.13 16.51,64.13 10.79,69.85 -1.27,69.85
  pour Top (isolate 0.406): -2.54,41.27 11.43,41.27 15.24,45.09 26.35,45.09 28.57,47.31 28.57,63.18 27.62,64.13 16.51,64.13 10.79,69.85 -2.54,69.85
AVCC
  Bottom 0.813: IC1.30 83.82,42.55 C17.1 87.95,43.82 L1.2
CLKOUT
  Top 0.406: 60.33,39.37 62.23,37.47 IC1.13 | 60.33,39.37 Q2.2 | C2.1 60.01,39.69 60.33,39.37
CLKOUT1
  Top 0.305: IC2.3 40.96,50.8 43.18,53.02 IC3.3
CS  (via drill 0.4)
  Top 0.305: IC3.16 43.18,62.23 40.64,59.69 IC2.16 | v59.05,53.34 58.74,53.66 58.74,55.88 58.74,57.47 59.05,57.79 SV2.5
  Bottom 0.305: JP5.5 36.2,72.39 36.2,64.77 40.64,60.33 IC2.16 40.64,57.47 43.5,54.61 58.1,54.61 59.05,53.66 v59.05,53.34
  Bottom 0.61: SV2.5 IC1.5
GND  (via drill 0.4, 0.6, 1 pad 1.68)
  Top 0.305: 50.8,53.98 IC3.9
  Top 0.61: IC4.15 20.95,27.3 21.91,28.26 21.91,32.7 22.86,33.66 25.4,33.66 26.99,35.24 v32.07,35.24
  Top 0.813: JP7.9 93.66,54.93 93.66,49.53 94.3,48.9 C10.2 | C11.2 93.03,27.62 93.98,28.57 JP8.9 | 36.83,56.52 50.16,56.52 50.8,55.88 50.8,53.98 51.12,53.66 53.34,53.66 55.88,51.12 IC2.9 | 33.66,57.79 34.92,56.52 36.83,56.52 | C21.2 36.83,59.69 36.83,56.52 | 33.66,57.79 33.66,67.31 34.61,68.26 C16.2 | 33.66,57.79 JP2.6 | IC9.3 51.75,17.14 | X2.2 77.79,4.45 78.42,3.81 JP12.1 85.41,3.81 86.36,4.76 86.36,7.62 87,8.26 89.22,8.26 93.98,13.02 93.98,14.29 94.3,14.61 JP9.9
  Top 1.016: C15.2 73.34,42.55 73.98,43.18 v73.98,44.13 73.98,55.56 v74.3,55.88 | JP5.9 42.55,73.02 43.5,73.98 v43.5,75.56
  Top 1.422: C23.- 42.86,4.45 42.23,5.08 D1.A 42.23,6.03
  Bottom 0.406: S3.1 23.79,77.44 23.5,77.47 23.5,77.79 22.54,78.74 17.46,78.74 16.51,77.79 | 16.51,77.79 15.56,78.74 13.02,78.74 12.06,77.79 LED1.K | 16.51,77.79 LED2.K | 69.22,29.84 69.22,28.57 | 69.22,29.84 IC7.2 | 69.22,31.11 69.22,29.84 | 69.22,31.11 IC7.3 | 69.22,32.39 69.22,31.11 | 69.22,32.39 IC7.4 | v69.22,33.97 69.22,32.39 | 69.22,28.57 IC7.1 | 69.22,28.57 v69.22,20.95
  Bottom 0.61: IC4.10 21.27,40.01 22.54,41.27 25.4,41.27 26.35,42.23 C5.+ | IC8.7 52.39,65.41 52.39,66.67 | 52.39,66.67 IC8.6 | 52.39,67.94 52.39,66.67 | 52.39,67.94 IC8.4 | 51.12,73.02 51.12,70.8 C19.2 52.39,69.53 52.39,67.94 | 52.39,67.94 IC8.5
  Bottom 0.813: 82.55,45.09 86.04,45.09 89.85,48.9 C10.2 | IC4.10 15.88,40.01 14.61,38.73 14.61,33.66 12.7,31.75 X1.5 12.93,29.62 15.24,27.3 IC4.15 | C16.2 39.69,70.8 40.64,71.75 JP5.9
  Bottom 1.016: 92.39,15.56 92.39,26.99 91.76,27.62 C11.2 | 92.39,15.56 C13.2 | 92.39,15.56 93.34,14.61 JP9.9 | 82.55,45.09 IC1.31 76.83,45.09 75.88,44.13 v73.98,44.13 | 82.55,45.09 C17.2 | 82.55,45.09 C9.2 | 53.05,77.44 53.34,77.15 64.45,77.15 JP10.6 74.3,75.56 | 74.3,75.56 JP6.2 78.11,77.47 84.45,77.47 JP6.10 88.58,75.56 89.53,74.61 C14.2 | 53.05,77.44 53.02,77.47 52.07,76.52 52.07,73.98 51.12,73.02 | 53.05,77.44 S1.1 | 23.5,77.47 S3.1 23.53,77.51 24.45,78.74 42.55,78.74 43.5,77.47 v43.5,75.56 | IC2.9 56.52,50.16 C20.2 54.61,46.67 54.61,44.13 | C3.2 C4.2 46.04,40.32 47.31,39.05 54.61,39.05 | 54.61,39.05 54.61,44.13 | 54.61,44.13 C1.2 57.78,44.13 59.37,42.55 IC1.11 C15.2 v69.22,33.97 | v74.3,55.88 74.3,75.56 | IC9.3 IC9.5 55.16,9.3 55.24,9.53 | 58.42,37.15 C2.2 54.61,39.05
  Bottom 1.27: 51.75,8.57 51.75,14.61 | 55.24,9.53 55.24,14.61
  Bottom 1.422: R9.1 62.23,11.43 60.33,9.53 55.24,9.53 IC9.5
  Bottom 1.676: 46.99,13.34 45.72,12.06 45.72,6.35 47.31,4.76 50.48,4.76 51.75,6.03 51.75,8.57 IC9.3 | X2.2 77.76,6.64 77.79,9.84 76.52,11.11 69.53,11.11 67.6,9.18 67.6,5.69 66.67,4.76 56.52,4.76 55.24,6.03 55.24,9.53
  other vias: 98.74,53.34 73.34,20.95 17.78,22.22 20.32,22.22 33.97,53.02 95.89,11.75 79.38,69.85 47.94,27.3 47.94,24.76 50.48,24.76 47.94,22.22 47.94,19.68 50.48,19.68 53.02,19.68 55.56,22.22 55.56,24.76 55.56,27.3 53.02,24.76 53.02,22.22 50.48,22.22 55.56,19.68 47.94,29.84 55.56,29.84 50.48,17.14 47.94,17.14 53.02,17.14 55.56,17.14 73.66,65.72 66.36,46.36 45.4,29.84 45.4,27.3 45.4,24.76 45.4,22.22 20.64,36.51 34.29,45.09 3.81,15.88 3.81,33.66 37.47,43.82 34.29,43.18 46.35,35.88 51.12,34.29 48.9,34.29 45.09,2.86 62.55,2.86 62.55,6.03 59.37,3.81 26.04,31.11 55.56,32.39 53.02,32.39 50.48,32.39
  pour Bottom (isolate 0.406, rank 6): -1.27,81.28 101.6,81.28 101.6,-1.27 -1.27,-1.27
  pour Top (isolate 0.406, rank 6): -2.54,82.55 102.87,82.55 102.87,-2.54 -2.54,-2.54
LED4
  Bottom 0.406: SJ2.2 R4.1 22.23,72.07 21.59,71.44 21.59,68.9 20.64,67.94 SV6.2
LED5
  Bottom 0.406: SJ3.2 R3.1 23.81,69.53 23.18,68.9 SV6.1
MISO  (via drill 0.4)
  Top 0.305: IC3.15 44.45,61.91 v43.81,61.28 43.18,60.64 IC2.15
  Bottom 0.305: SV2.7 58.42,55.25 43.81,55.25 43.18,55.88 IC2.15 | JP5.7 37.47,72.39 37.47,65.41 41.59,61.28 v43.81,61.28
  Bottom 0.406: IC1.7 69.22,52.71 70.48,53.98 70.48,67.31 66.99,70.8 61.59,70.8 60.96,71.44 JP10.1
  Bottom 0.61: SV2.7 IC1.7
MOSI
  Top 0.305: IC2.14 IC3.14
  Bottom 0.305: SV2.6 60.01,55.25 59.37,55.88 46.35,55.88 45.72,56.52 IC2.14 45.72,60.01 45.4,60.33 41.59,60.33 36.83,65.09 36.83,73.98 35.56,75.25 JP5.6
  Bottom 0.406: IC1.6 68.9,55.25 69.53,55.88 69.53,66.99 66.67,69.85 60.64,69.85 59.69,70.8 59.69,72.39 59.69,73.66 60.33,74.3 62.23,74.3 JP10.4
  Bottom 0.61: SV2.6 IC1.6
N$1
  Bottom 0.406: IC4.5 25.4,34.93 26.99,36.51 C6.-
N$2
  Bottom 0.406: IC4.4 25.72,32.39 27.3,33.97 C6.+
N$3
  Bottom 0.406: IC4.3 26.99,29.84 C7.-
N$4
  Bottom 0.406: IC4.2 26.67,27.3 C8.+
N$5
  Bottom 0.406: IC4.6 25.4,37.47 27.62,39.69 C5.-
N$6  (via drill 1 pad 1.68)
  other vias: 33.02,17.14
N$7  (via drill 1 pad 1.68)
  other vias: 15.24,6.99
N$8
  Top 0.406: C7.+ 27.94,26.99 25.72,24.76 IC4.1
N$9
  Top 0.305: IC2.7 50.48,50.8 48.26,53.02 IC3.7
  Top 0.406: Q1.2 52.7,41.27 52.07,41.91 C4.1
  Bottom 0.406: IC2.7 50.8,45.4 52.7,43.5 Q1.2 52.7,41.27
N$10
  Bottom 0.406: IC6.4 16.51,60.33 17.46,59.37 24.77,59.37 25.72,60.33 JP2.3
N$11  (via drill 0.4)
  Top 0.305: IC3.2 41.91,53.02 41.59,52.71 38.73,52.71 38.1,52.07 IC2.2
  Top 0.406: v32.7,56.52 32.7,49.85 33.34,49.21 37.47,49.21 38.1,49.85 IC2.2
  Bottom 0.406: JP2.4 32.07,60.33 32.7,59.69 v32.7,56.52
N$12
  Top 0.305: IC3.8 49.53,53.34 50.16,52.71 52.7,52.71 53.34,52.07 IC2.8
  Top 0.406: Q1.1 52.7,46.36 51.12,44.77 C3.1
  Bottom 0.406: Q1.1 52.7,46.36 53.34,46.99 IC2.8
N$13
  Bottom 0.406: IC1.32 83.82,47.62 C9.1
N$14  (via drill 1 pad 1.68)
  other vias: 12.7,6.99
N$15
  Bottom 0.813: R5.1 86.68,7.3 87.63,6.35 LED3.A
N$16
  Top 1.422: 70.17,13.97 D2.C 61.91,13.97 60.01,12.06 60.01,7.3 57.15,4.45 C22.+ C23.+ 48.9,4.45 48.26,5.08 48.26,9.53 IC9.1
  Top 1.676: 70.17,13.97 F1.1
N$17
  Bottom 0.406: R2.2 IC6.8
  Bottom 0.61: IC6.8 SJ5.2
N$18
  Top 0.406: IC1.12 61.91,40.01 60.33,41.59 | 60.33,44.45 Q2.1 60.33,41.59 | C1.1 60.33,41.59
N$19
  Top 0.813: IC9.4 57.47,12.06 | 57.47,12.06 R9.2 | 57.47,12.06 58.42,13.02 R10.1
N$20
  Top 0.305: IC3.12 48.26,61.91 50.8,59.37 IC2.12
  Bottom 0.305: IC2.12 50.8,59.69 51.12,60.01 56.52,60.01 57.47,59.05 SJ1.2
N$21  (via drill 1 pad 1.68)
  other vias: 22.86,4.45
N$22
  Top 0.406: JP4.3 7.94,55.56 10.79,55.56 12.7,57.47 | 12.7,58.42 JP3.2 12.7,57.47 | JP1.2 21.59,47.94 19.05,50.48 IC6.6 19.05,56.2 17.78,57.47 12.7,57.47
N$23
  Top 0.406: JP4.4 5.71,55.25 6.99,56.52 9.84,56.52 10.16,56.83 | 10.16,56.83 JP3.7 | R1.1 22.54,48.9 21.59,49.85 IC6.7 21.59,55.25 18.1,58.74 14.61,58.74 13.65,59.69 12.06,59.69 11.11,58.74 11.11,57.79 10.16,56.83
N$24
  Bottom 0.406: IC6.1 24.13,62.23 24.77,62.87 JP2.1
N$25
  Top 0.406: JP1.1 19.05,47.94 18.1,48.9 R1.2
N$26
  Top 0.305: IC2.4 43.18,51.75 44.45,53.02 IC3.4
  Top 0.406: IC2.4 43.18,49.85 41.91,48.58 SV5.3
N$27
  Top 0.305: IC2.5 IC3.5
  Top 0.406: IC2.5 45.72,49.85 44.45,48.58 SV5.4
N$28
  Top 0.305: IC3.6 46.99,53.02 48.26,51.75 IC2.6
  Top 0.406: IC2.6 48.26,49.85 46.99,48.58 SV5.5
N$29  (via drill 0.4)
  Top 0.305: IC3.11 49.53,62.23 IC2.11 53.34,57.79 54.93,56.2 v54.93,53.66
  Bottom 0.305: SV5.1 36.83,52.07 38.1,53.34 54.61,53.34 v54.93,53.66
N$30  (via drill 0.4)
  Top 0.305: IC3.10 50.8,63.5 IC2.10 v55.88,53.02
  Bottom 0.305: SV5.2 39.37,52.07 40.01,52.71 55.56,52.71 v55.88,53.02
N$31
  Top 0.406: IC2.1 35.56,52.07 36.83,53.34 40.32,53.34 40.64,53.66 IC3.1 40.64,54.61
  Bottom 0.406: IC2.1 35.56,54.29 36.83,55.56 36.83,61.91 35.88,62.87 JP2.2
N$32  (via drill 1 pad 1.68)
  other vias: 25.4,4.45
N$33  (via drill 1 pad 1.68)
  other vias: 25.4,6.99
N$34  (via drill 1 pad 1.68)
  other vias: 22.86,6.99
N$35  (via drill 1 pad 1.68)
  other vias: 20.32,6.99
N$36  (via drill 1 pad 1.68)
  other vias: 20.32,4.45
N$37  (via drill 1 pad 1.68)
  other vias: 17.78,4.45
N$38  (via drill 1 pad 1.68)
  other vias: 17.78,6.99
N$40  (via drill 1 pad 1.68)
  other vias: 15.24,4.45
N$41  (via drill 1 pad 1.68)
  other vias: 12.7,4.45
N$44  (via drill 1 pad 1.68)
  other vias: 12.7,1.91
N$45  (via drill 1 pad 1.68)
  other vias: 15.24,1.91
N$46  (via drill 1 pad 1.68)
  other vias: 17.78,1.91
N$47  (via drill 1 pad 1.68)
  other vias: 20.32,1.91
N$48
  Bottom 0.305: IC7.7 75.56,29.84 75.88,29.84 76.2,29.53 76.2,27.94 75.56,27.3 SJ4.1
N$49  (via drill 1 pad 1.68)
  other vias: 22.86,1.91
N$50  (via drill 1 pad 1.68)
  other vias: 25.4,1.91
N$51  (via drill 1 pad 1.68)
  other vias: 17.78,9.53
N$52  (via drill 1 pad 1.68)
  other vias: 17.78,12.06
N$53  (via drill 1 pad 1.68)
  other vias: 17.78,14.61
N$54  (via drill 1 pad 1.68)
  other vias: 17.78,17.14
N$55  (via drill 1 pad 1.68)
  other vias: 17.78,19.68
N$56  (via drill 1 pad 1.68)
  other vias: 20.32,19.68
N$57  (via drill 1 pad 1.68)
  other vias: 22.86,19.68
N$58  (via drill 1 pad 1.68)
  other vias: 25.4,19.68
N$59  (via drill 1 pad 1.68)
  other vias: 25.4,17.14
N$60  (via drill 1 pad 1.68)
  other vias: 22.86,17.14
N$61  (via drill 1 pad 1.68)
  other vias: 20.32,17.14
N$62  (via drill 1 pad 1.68)
  other vias: 20.32,14.61
N$65  (via drill 1 pad 1.68)
  other vias: 20.32,12.06
N$66  (via drill 1 pad 1.68)
  other vias: 20.32,9.53
N$68  (via drill 1 pad 1.68)
  other vias: 22.86,9.53
N$69  (via drill 1 pad 1.68)
  other vias: 22.86,12.06
N$70  (via drill 1 pad 1.68)
  other vias: 22.86,14.61
N$71  (via drill 1 pad 1.68)
  other vias: 25.4,14.61
N$72  (via drill 1 pad 1.68)
  other vias: 25.4,12.06
N$73  (via drill 1 pad 1.68)
  other vias: 25.4,9.53
N$74  (via drill 1 pad 1.68)
  other vias: 27.94,9.53
N$75  (via drill 1 pad 1.68)
  other vias: 27.94,12.06
N$76  (via drill 1 pad 1.68)
  other vias: 30.48,12.06
N$81  (via drill 1 pad 1.68)
  other vias: 33.02,6.99
N$82  (via drill 1 pad 1.68)
  other vias: 33.02,4.45
N$83  (via drill 1 pad 1.68)
  other vias: 33.02,1.91
N$84  (via drill 1 pad 1.68)
  other vias: 35.56,1.91
N$85  (via drill 1 pad 1.68)
  other vias: 35.56,4.45
N$86  (via drill 1 pad 1.68)
  other vias: 30.48,4.45
N$87  (via drill 1 pad 1.68)
  other vias: 30.48,1.91
N$88  (via drill 1 pad 1.68)
  other vias: 27.94,1.91
N$89  (via drill 1 pad 1.68)
  other vias: 27.94,4.45
N$90  (via drill 1 pad 1.68)
  other vias: 27.94,6.99
N$91  (via drill 1 pad 1.68)
  other vias: 30.48,6.99
N$94  (via drill 1 pad 1.68)
  other vias: 30.48,9.53
N$95  (via drill 1 pad 1.68)
  other vias: 27.94,19.68
N$96  (via drill 1 pad 1.68)
  other vias: 30.48,19.68
N$97  (via drill 1 pad 1.68)
  other vias: 30.48,17.14
N$98  (via drill 1 pad 1.68)
  other vias: 27.94,17.14
N$100  (via drill 1 pad 1.68)
  other vias: 27.94,14.61
N$101  (via drill 1 pad 1.68)
  other vias: 30.48,14.61
N$103  (via drill 1 pad 1.68)
  other vias: 33.02,12.06
N$104  (via drill 1 pad 1.68)
  other vias: 33.02,9.53
N$105
  Top 1.676: IC9.2 50.05,12.81 49.73,13.13 43.38,13.13 42.23,14.29 D1.C 42.23,18.1 41.27,19.05 37.78,19.05 36.51,18.73 L2.1
  pour Top (isolate 0.406, no thermals): 40.64,10.48 48.26,10.48 48.9,11.11 50.48,11.11 50.8,11.43 50.8,13.97 50.48,14.29 46.04,14.29 45.09,15.24 45.09,17.78 41.91,20.95 35.24,20.95 34.92,20.64 34.92,16.51 35.24,16.19 38.73,16.19 39.69,15.24 39.69,14.92 39.69,11.43
N$106  (via drill 1 pad 1.68)
  other vias: 35.56,9.53
N$108
  Bottom 0.305: R11.2 31.75,66.36 31.75,76.83 28.89,76.83 28.89,75.56 26.35,75.56 26.35,75.88 SJ7.2
  Bottom 0.406: SJ7.2 24.77,76.52 23.5,76.2 20.32,76.2 | S3.2 19.02,77.44 19.05,77.47 20.32,76.2 | SV6.3 18.1,67.31 20.32,69.53 20.32,76.2
N$109  (via drill 1 pad 1.68)
  other vias: 35.56,12.06
N$110  (via drill 1 pad 1.68)
  other vias: 38.1,12.06
N$111  (via drill 1 pad 1.68)
  other vias: 38.1,9.53
N$114  (via drill 1 pad 1.68)
  other vias: 35.56,6.99
N$115  (via drill 1 pad 1.68)
  other vias: 38.1,6.99
N$116  (via drill 1 pad 1.68)
  other vias: 38.1,4.45
N$119  (via drill 1 pad 1.68)
  other vias: 38.1,1.91
N$122  (via drill 1 pad 1.68)
  other vias: 33.02,14.61
N$123  (via drill 1 pad 1.68)
  other vias: 35.56,14.61
N$127  (via drill 1 pad 1.68)
  other vias: 38.1,14.61
N$168
  Top 0.406: R4.2 14.92,72.07 13.97,73.02 LED2.A
N$169
  Top 0.406: R3.2 16.19,69.53 13.02,72.71 13.02,75.56 12.38,76.2 10.16,76.2 9.53,76.83 LED1.A
PA0
  Bottom 0.305: SV1.1 84.45,67.94 87,65.41 JP7.1
  Bottom 0.61: IC1.40 SV1.1
PA1
  Bottom 0.305: SV1.2 85.09,65.41 86.36,64.13 95.25,64.13 JP7.2
  Bottom 0.61: IC1.39 SV1.2
PA2
  Bottom 0.305: SV1.3 JP7.3
  Bottom 0.61: IC1.38 SV1.3
PA3
  Bottom 0.305: JP7.4 95.25,61.59 93.66,61.59 | 93.66,61.59 93.34,61.59 | SV1.4 86.36,60.33 87.63,61.59 93.66,61.59
  Bottom 0.61: IC1.37 SV1.4
PA4
  Bottom 0.305: SV1.5 85.41,57.79 87.95,60.33 JP7.5
  Bottom 0.61: IC1.36 SV1.5
PA5
  Bottom 0.305: JP7.6 95.25,59.05 88.27,59.05 84.45,55.25 SV1.6
  Bottom 0.61: IC1.35 SV1.6
PA6
  Bottom 0.305: JP7.7 91.12,57.79 90.49,57.15 90.49,53.66 89.53,52.71 SV1.7
  Bottom 0.61: IC1.34 SV1.7
PA7
  Bottom 0.305: JP7.8 95.25,56.52 91.76,56.52 91.12,55.88 91.12,53.34 89.85,52.07 87.31,52.07 85.41,50.16 SV1.8
  Bottom 0.61: IC1.33 SV1.8
PB0
  Top 0.305: SV2.1 58.42,67.94 57.78,68.58 48.26,68.58 45.09,71.75 31.75,71.75 JP5.1
  Bottom 0.406: SJ3.1 29.84,69.53 30.48,70.17 JP5.1
  Bottom 0.61: SV2.1 IC1.1
PB1
  Top 0.305: JP5.2 29.84,75.56 29.21,74.93 29.21,72.39 30.48,71.12 44.77,71.12 47.94,67.94 57.47,67.94 60.01,65.41 SV2.2
  Bottom 0.406: SJ2.1 27.43,72.2 30.48,75.25 JP5.2
  Bottom 0.61: SV2.2 IC1.2
PB2
  Top 0.305: JP5.3 33.02,73.66 31.75,74.93 31.75,76.2 31.11,76.83 29.21,76.83 28.57,76.2 28.57,72.07 30.16,70.48 44.45,70.48 47.62,67.31 57.15,67.31 57.78,66.67 57.78,63.82 58.74,62.87 SV2.3
  Bottom 0.305: SJ1.1 67.63,62.55 67.31,62.87 IC1.3
  Bottom 0.61: SV2.3 IC1.3
PC0  (via drill 0.4)
  Top 0.305: v75.56,40.96 75.88,41.27 75.88,62.87 75.25,63.5 66.36,63.5 65.72,64.13 v58.74,64.13
  Bottom 0.305: SV3.1 IC1.22 77.79,22.22 76.83,23.18 76.83,29.84 75.56,31.11 74.3,31.11 | 74.3,31.11 73.03,31.11 72.71,31.43 72.71,33.34 73.03,33.66 75.25,33.66 75.56,33.97 v75.56,40.96 76.2,41.59 90.17,41.59 93.66,45.09 JP8.1 | 74.3,31.11 IC7.6 | v58.74,64.13 58.74,63.82 57.78,62.87 51.12,62.87 48.58,65.41 IC8.2
  Bottom 0.406: SV3.1 83.82,18.1 R7.2
  Bottom 0.61: SV3.1 IC1.22
PC1  (via drill 0.4)
  Top 0.305: v76.52,40.64 76.52,63.18 75.56,64.13 66.99,64.13 v66.67,64.45
  Bottom 0.305: SV3.2 IC1.23 78.11,24.76 77.47,25.4 77.47,30.16 76.2,31.43 76.2,32.39 | JP8.2 95.25,43.82 93.34,43.82 90.49,40.96 76.83,40.96 v76.52,40.64 76.2,40.32 76.2,32.39 | 76.2,32.39 IC7.5 | v66.67,64.45 66.36,64.13 60.01,64.13 58.1,62.23 50.8,62.23 48.9,64.13 IC8.1
  Bottom 0.406: R6.2 85.72,17.78 85.72,24.13 85.09,24.76 SV3.2
  Bottom 0.61: SV3.2 IC1.23
PC2  (via drill 0.4)
  Top 0.305: JP6.1 76.2,72.71 77.15,71.75 79.38,71.75 81.92,69.21 81.92,67.31 82.55,66.67 84.77,66.67 89.53,61.91 89.53,43.18 v91.76,40.96
  Bottom 0.305: SV3.3 IC1.24 78.74,27.3 78.11,27.94 78.11,30.48 76.83,31.75 76.83,37.78 78.11,39.05 90.49,39.05 92.08,40.64 | 92.08,40.64 JP8.3 | 92.08,40.64 v91.76,40.96
  Bottom 0.61: IC1.24 SV3.3
PC3
  Top 0.305: JP8.4 96.52,43.18 95.89,43.82 91.44,43.82 90.81,44.45 90.81,62.55 86.04,67.31 86.04,69.21 85.09,70.17 82.87,70.17 81.6,71.44 81.6,72.71 JP6.5
  Bottom 0.305: SV3.4 IC1.25 79.69,29.84 77.47,32.07 77.47,37.15 78.74,38.42 90.81,38.42 93.66,41.27 95.25,41.27 JP8.4
  Bottom 0.61: IC1.25 SV3.4
PC4  (via drill 0.4)
  Top 0.305: JP6.3 79.06,73.02 82.55,69.53 84.77,69.53 85.41,68.9 85.41,66.99 90.17,62.23 90.17,43.82 JP8.5 | v91.12,36.51 91.12,33.02 90.49,32.39 SV3.5
  Bottom 0.305: IC1.26 SV3.5 | JP8.5 93.98,39.37 v91.12,36.51
  Bottom 0.61: IC1.26 SV3.5
PC5
  Top 0.305: JP8.6 97.79,41.27 97.79,46.04 97.16,46.67 92.08,46.67 91.44,47.31 91.44,64.77 88.27,67.94 88.27,70.8 JP6.9
  Bottom 0.305: IC1.27 SV3.6 92.08,34.93 93.34,36.2 94.61,36.2 95.25,36.83 95.25,38.1 96.52,39.37 JP8.6
  Bottom 0.61: IC1.27 SV3.6
PC6
  Bottom 0.305: SV3.7 85.09,37.47 87,35.56 91.76,35.56 93.66,37.47 JP8.7
  Bottom 0.61: IC1.28 SV3.7
PC7  (via drill 0.4)
  Top 0.305: v90.17,40.01 91.12,38.73 95.25,38.73 JP8.8
  Bottom 0.305: SV3.8 v90.17,40.01
  Bottom 0.61: IC1.29 SV3.8
PD0  (via drill 0.4)
  Top 0.305: JP9.1 93.34,24.76 92.71,24.76 89.53,24.76 85.41,28.89 70.8,28.89 IC1.14 SV4.1 53.98,34.93 53.66,35.24 53.66,37.78 52.39,39.05 46.04,39.05 44.13,40.96 20.95,40.96 v18.73,38.73
  Bottom 0.305: v18.73,38.73 18.73,35.56 18.1,34.93 IC4.12
PD1
  Top 0.305: JP9.2 95.25,23.49 93.03,23.49 92.08,23.49 89.85,23.49 85.09,28.26 70.48,28.26 66.36,32.39 IC1.15 SV4.2 60.01,32.39 58.1,34.29 53.66,34.29 53.02,34.93 53.02,37.47 52.07,38.42 45.72,38.42 43.81,40.32 30.8,40.32 28.57,38.42 20,38.42 19.05,37.47 IC4.11
PD2  (via drill 0.4)
  Top 0.305: SV4.3 IC1.16 66.36,29.84 69.85,26.35 86.04,26.35 88.9,23.49 89.53,22.86 90.17,22.22 91.12,22.22 JP9.3 | v66.67,34.29 67.63,35.24 v67.63,56.2
  Bottom 0.305: v66.67,34.29 66.36,33.97 66.36,30.48 65.72,29.84 IC1.16 | 67.63,57.47 67.88,57.53 SJ1.3 67.63,57.47 | v67.63,56.2 67.63,57.47
PD3
  Top 0.305: SV4.4 IC1.17 66.36,27.3 67.94,25.72 85.72,25.72 90.49,20.95 95.25,20.95 JP9.4
PD4
  Top 0.305: SV4.5 IC1.18 | IC1.18 | IC1.18 65.72,23.81 72.71,23.81 77.79,23.81 | 77.79,23.81 | 77.79,23.81 83.66,23.81 86.68,23.81 90.81,19.68 JP9.5
PD5
  Top 0.305: SV4.6 IC1.19 | IC1.19 | IC1.19 66.04,22.22 66.36,22.22 67.31,23.18 85.41,23.18 86.04,23.18 86.36,23.18 91.12,18.41 95.25,18.41 JP9.6
PD6
  Top 0.305: SV4.7 IC1.20 75.25,19.68 76.52,20.95 87.63,20.95 91.44,17.14 JP9.7
PD7
  Top 0.305: SV4.8 61.59,17.14 62.87,18.41 75.56,18.41 76.83,19.68 IC1.21 87.95,19.68 89.22,18.41 | JP9.8 95.25,15.88 91.76,15.88 89.22,18.41 | 89.22,18.41
R_IN
  Top 0.305: X1.3 13.65,24.13 13.97,24.45 13.97,30.48 15.56,32.39 IC4.13
RESET  (via drill 0.4)
  Top 0.305: IC3.17 v41.91,63.18 41.91,62.87 38.1,59.05 IC2.17 | v57.78,60.01 58.1,59.69 58.1,50.48 60.96,47.62 IC1.9
  Top 0.406: S1.2 48.54,77.19 49.85,75.88 49.85,72.39 | 49.85,72.39 R8.1 | 49.85,72.39 51.12,71.12 65.41,71.12 66.04,71.75 JP10.5 67.31,74.3 80.01,74.3 JP6.6
  Bottom 0.305: v41.91,63.18 42.23,62.87 48.26,62.87 50.48,60.64 57.15,60.64 v57.78,60.01
  Bottom 0.406: IC1.9 67.31,47.62 72.39,52.71 72.39,67.94 67.31,73.02 JP10.5
SCK  (via drill 0.4)
  Top 0.305: IC3.13 46.99,61.91 48.26,60.64 IC2.13 | v62.87,56.52 62.87,50.48 62.55,50.16 SV2.8
  Bottom 0.305: v62.87,56.52 48.9,56.52 48.26,57.15 IC2.13 48.26,61.59 47.62,62.23 41.59,62.23 38.1,65.72 38.1,71.12 39.37,72.39 39.37,74.3 JP5.8
  Bottom 0.406: IC1.8 68.26,50.16 71.44,53.34 71.44,67.63 67.31,71.75 64.77,71.75 JP10.3
  Bottom 0.61: SV2.8 IC1.8
SJ7
  Top 0.305: SV2.4 59.05,60.33 57.15,62.23 57.15,66.36 56.83,66.67 47.31,66.67 44.13,69.85 29.84,69.85 27.94,71.75 27.94,76.52 28.89,77.47 32.07,77.47 33.02,76.52 JP5.4
  Bottom 0.406: SV2.4 IC1.4 | SJ7.1 27.62,77.79 33.02,77.79 JP5.4
  Bottom 0.61: SV2.4 IC1.4
T_OUT
  Top 0.305: X1.2 14.08,21.39 14.61,21.91 14.61,29.21 15.24,29.84 IC4.14
V_CAN
  Top 0.61: JP4.8 3.49,58.74 3.49,52.07 4.13,51.44 JP3.9
  Bottom 0.61: JP3.9 13.65,51.44 14.92,50.16 JP2.11 JP2.9
V_IN
  Top 2.184: X2.1 72.71,8.26 77.79,13.34 F1.2
  Bottom 0.813: 40.01,13.97 40.01,15.24 | 40.01,14.29 40.01,14.13 | JP2.14 JP2.12
  Bottom 1.016: 40.01,14.29 40.01,15.24 30.48,24.76 30.48,30.8 29.53,31.75 29.53,33.02 30.48,33.97 JP2.14 JP2.12 | 40.01,13.97 40.01,2.54 41.27,1.27 71.44,1.27 72.71,2.54 X2.1
VCC
  Top 0.61: JP2.7 26.99,56.2 22.23,56.2 19.05,59.37 IC6.3
  Bottom 0.406: IC6.3 C18.1

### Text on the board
Top: FG | 2009
Bottom: 03/09 | Fabian Greif
tPlace: Boot | Reset | CAN | ISP | JTAG | PORTB | PORTA | PORTC | Gnd | +5V | PORTD | RS232 | GND | +
bNames: PB2 | PD2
